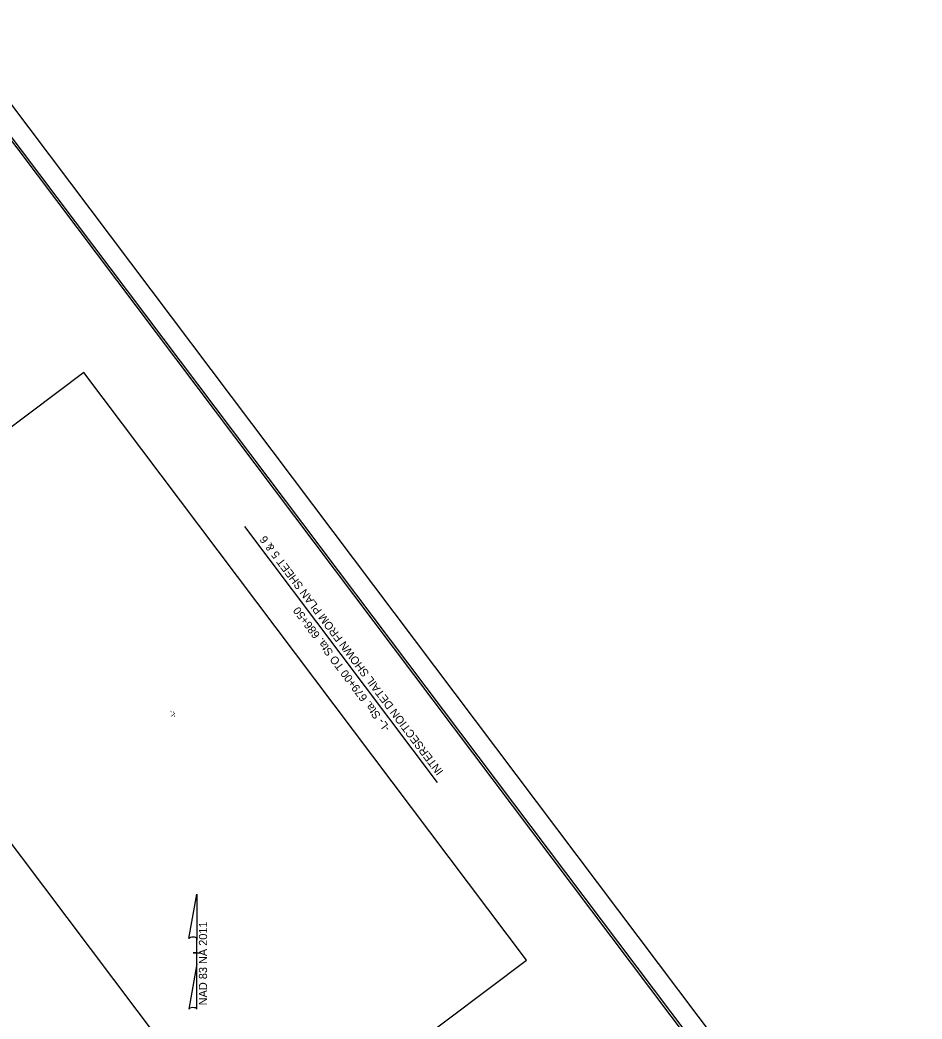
# Model space of a CAD drawing. Extents: x 1262861 to 1264804, y 775326 to 777329.
# Drawn here: x 1263867 to 1264804, y 776290 to 777329 of the extents above; entities that cross this region are included whole.
import ezdxf

# ---------------------------------------------------------------- set-up
doc = ezdxf.new("R2010")
doc.units = 0
for name, color, linetype in [('Old_Level_1', 7, 'Continuous'), ('Prop Dimension', 7, 'Continuous'), ('Prop Horizontal Alignment Curve and Spiral Data', 7, 'Continuous'), ('Sheet Plot Border Inside CELL', 7, 'Continuous'), ('Sheet Plot Border Outside CELL', 7, 'Continuous'), ('Sheet Typical CELL', 7, 'Continuous')]:
    doc.layers.add(name, color=color, linetype=linetype)

msp = doc.modelspace()

# ---------------------------------------------------------------- linework, layer by layer
at = {"layer": 'Old_Level_1'}
for p, q in [((1264042.2, 776374.1), (1264050.4, 776420.4)), ((1264050.5, 776420.4), (1264050.4, 776420.4)), ((1264050.5, 776420.4), (1264050.4, 776420.4)), ((1264050.5, 776420.4), (1264050.5, 776372.6)), ((1264050.5, 776347.8), (1264050.5, 776374)), ((1264050.5, 776372.6), (1264050.5, 776374)), ((1264046.5, 776359.4), (1264046.4, 776359.4)), ((1264046.5, 776359.4), (1264054.5, 776359.4)), ((1264050, 776359.4), (1264046.5, 776359.4)), ((1264050.5, 776347.8), (1264042.1, 776300.6)), ((1264050.5, 776300.8), (1264050.5, 776347.8))]:
    msp.add_line(p, q, dxfattribs=at)
for centre, start_param, end_param in [((1264046.4, 776373.6), 0.216388, 2.908219), ((1264046.3, 776300.4), 0.201328, 3.141593)]:
    msp.add_ellipse(centre, major_axis=(4.23, -0.03), ratio=0.461098, start_param=start_param, end_param=end_param, dxfattribs=at)
at = {"layer": 'Prop Horizontal Alignment Curve and Spiral Data'}
msp.add_line((1264300.5, 776536.4), (1264100.1, 776802.5), dxfattribs=at)
at = {"layer": 'Sheet Plot Border Inside CELL'}
msp.add_lwpolyline([(1264780.2, 775982.9), (1263777.9, 777313.6), (1262935.2, 776678.9), (1263937.5, 775348.2)], close=True, dxfattribs=at)
at = {"layer": 'Sheet Plot Border Outside CELL'}
msp.add_lwpolyline([(1262916.5, 776670.5), (1263929.4, 775325.7), (1264804, 775984.5), (1263791.2, 777329.3)], close=True, dxfattribs=at)
at = {"layer": 'Sheet Typical CELL'}
msp.add_line((1263783.4, 777302.1), (1264685.9, 776104), dxfattribs=at)
msp.add_lwpolyline([(1264392.9, 776351.8), (1263932.9, 776962.7), (1263649.3, 776749.1), (1264109.4, 776138.3)], close=True, dxfattribs=at)

# ---------------------------------------------------------------- texts
at = {"layer": 'Old_Level_1'}
msp.add_text('NAD 83 NA 2011', height=8.5, rotation=89.9761, dxfattribs=at).set_placement((1264061, 776304.7))
at = {"layer": 'Prop Dimension'}
msp.add_text('-L-', height=5, rotation=126.9874, dxfattribs=at).set_placement((1264029.4, 776605.6))
at = {"layer": 'Prop Horizontal Alignment Curve and Spiral Data'}
for s, p in [('INTERSECTION DETAIL SHOWN FROM PLAN SHEET 5 & 6 ', (1264306.9, 776547.9)), ('-L- Sta. 679+00 TO Sta. 686+50', (1264252, 776593))]:
    msp.add_text(s, height=8.32, rotation=126.9874, dxfattribs=at).set_placement(p)

doc.saveas('drawing.dxf')
